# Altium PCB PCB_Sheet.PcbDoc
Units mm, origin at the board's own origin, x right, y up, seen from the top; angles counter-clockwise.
Board outline 50.61 x 50.61 mm, 2 copper layers (Top Layer, Bottom Layer); 8 components, 17 nets, 42 pads, 0 vias.
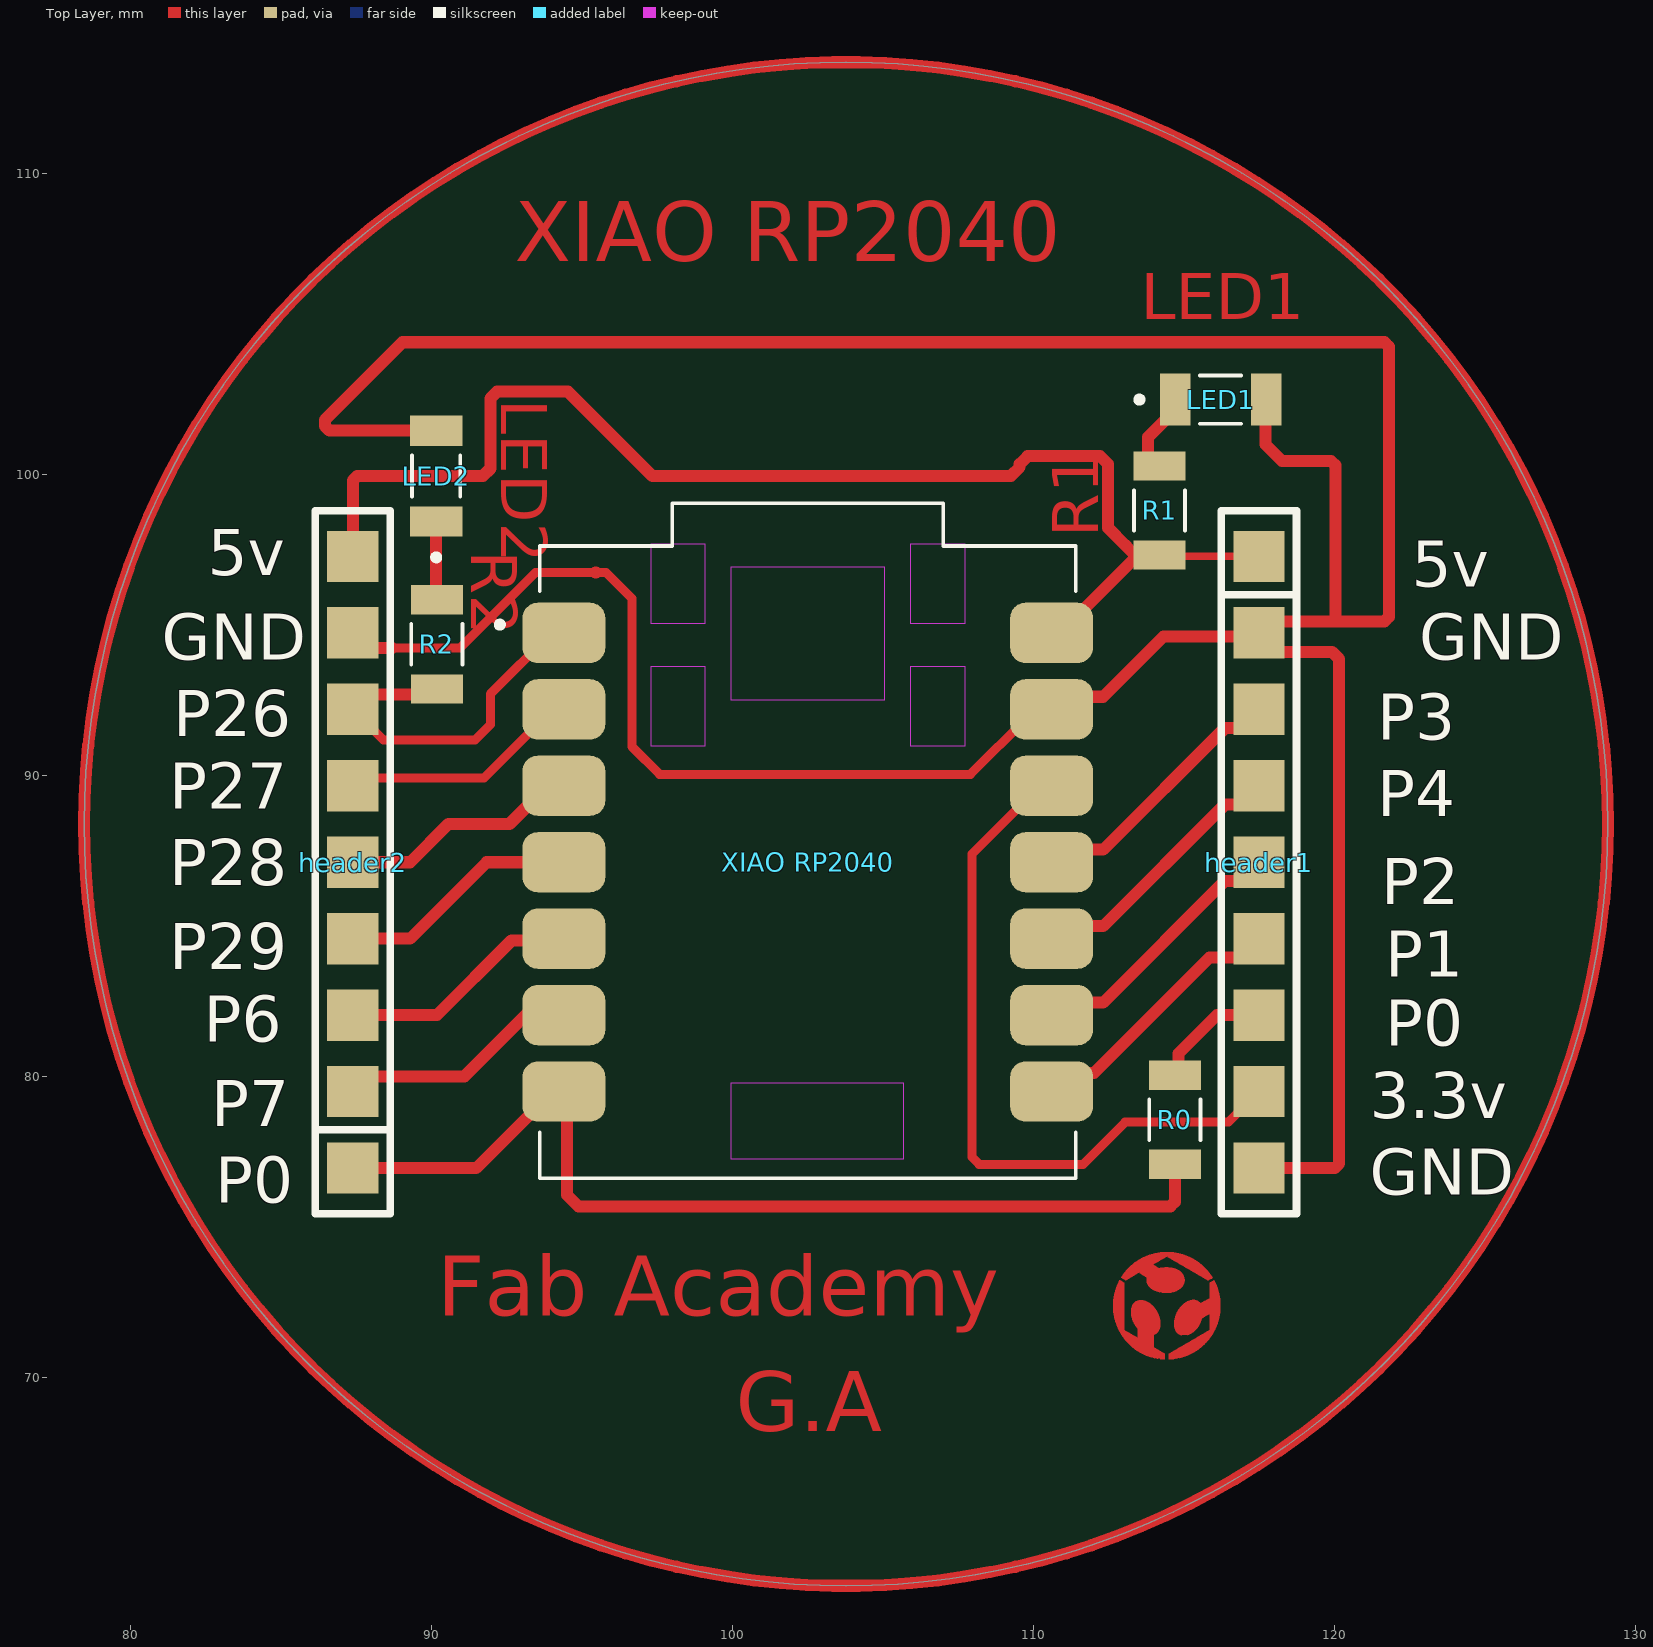
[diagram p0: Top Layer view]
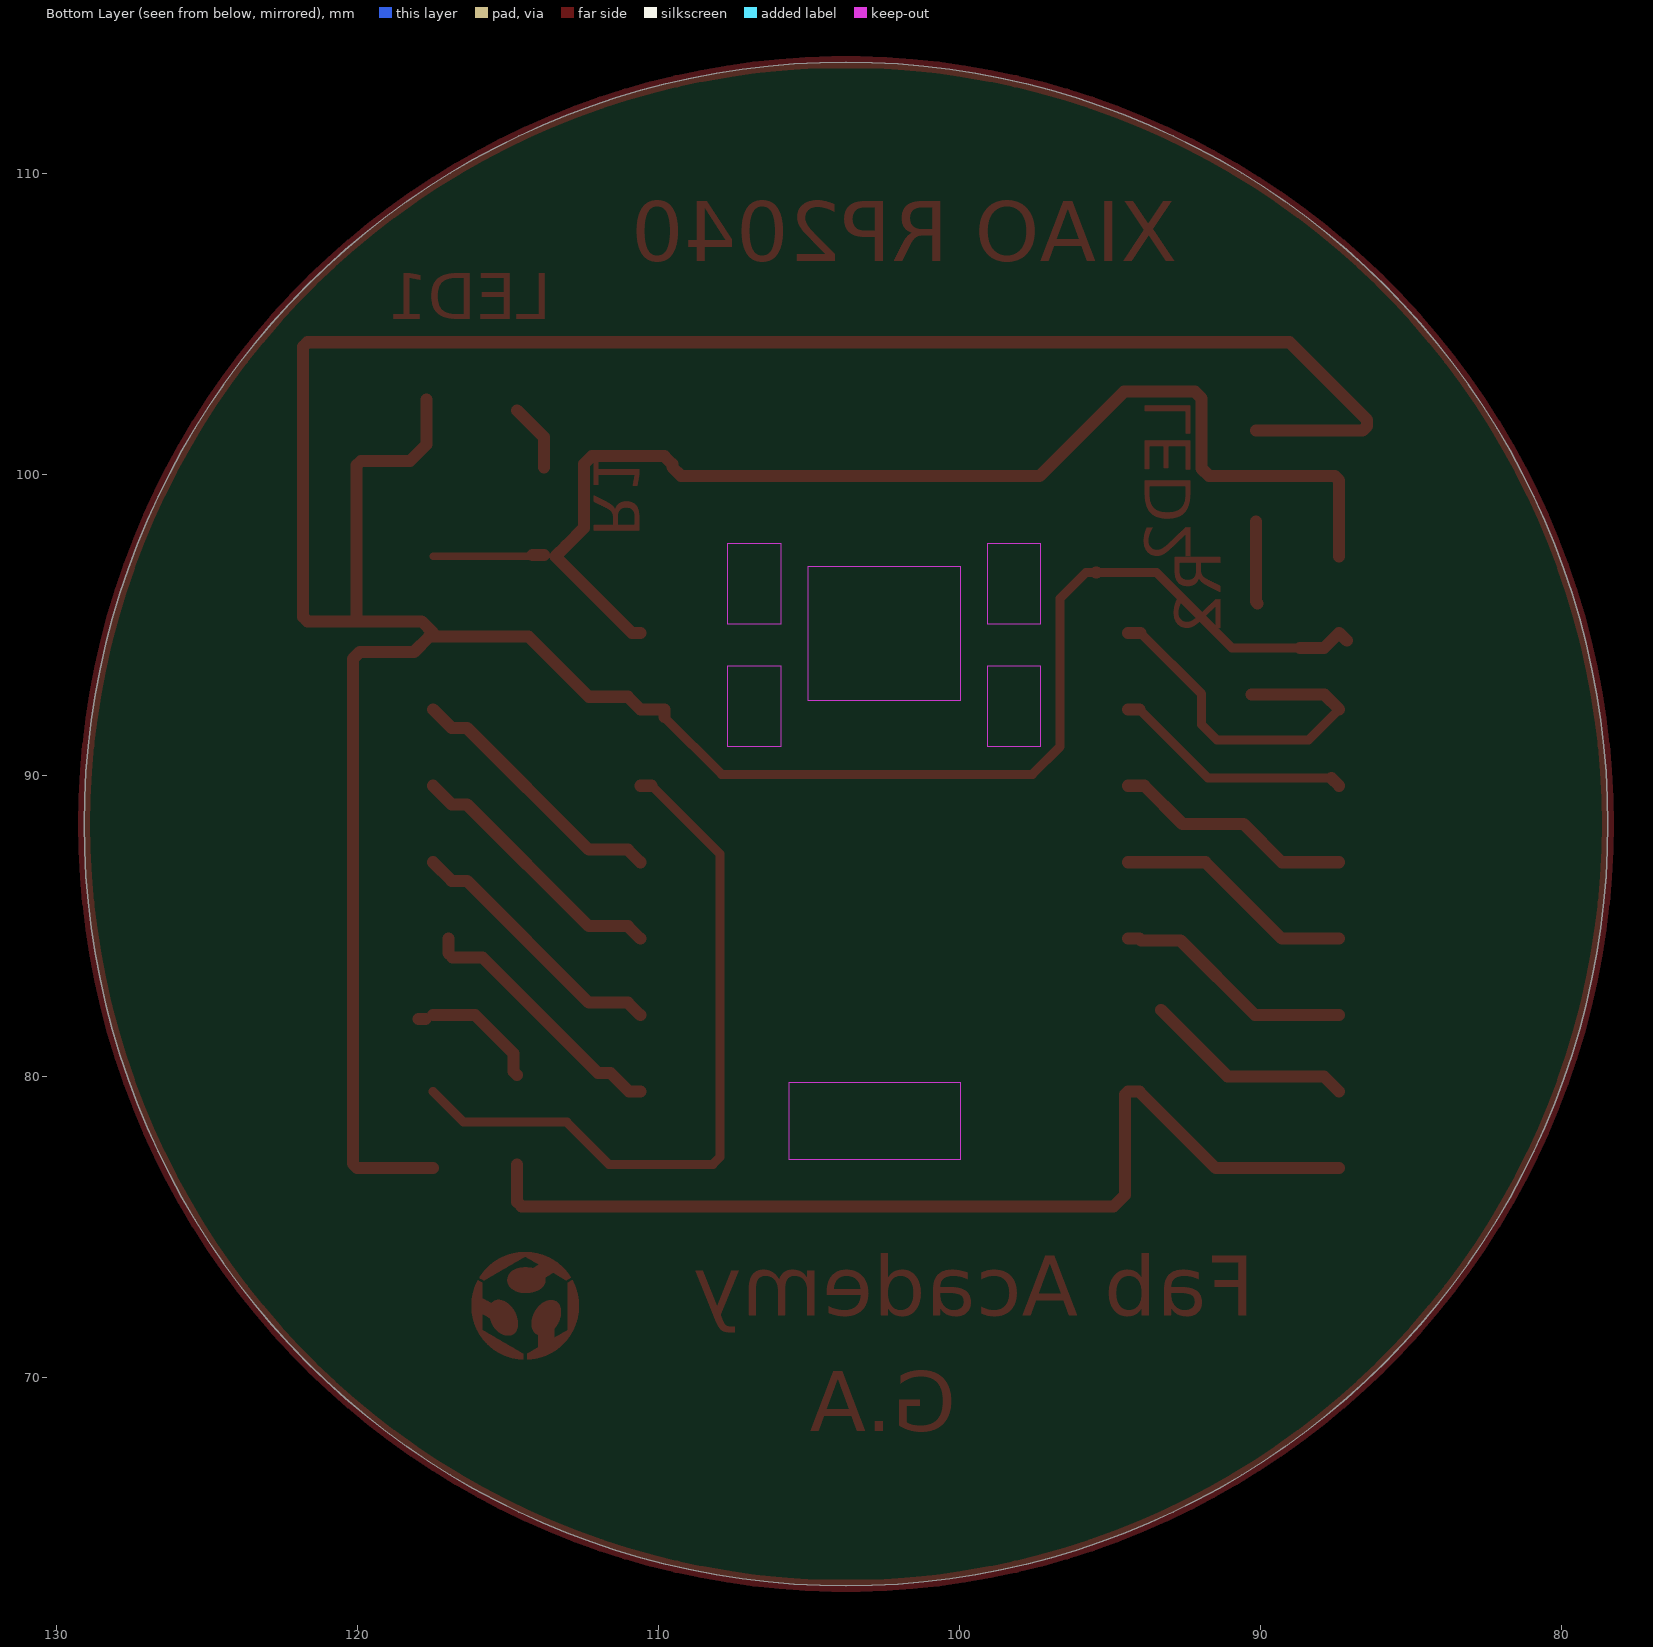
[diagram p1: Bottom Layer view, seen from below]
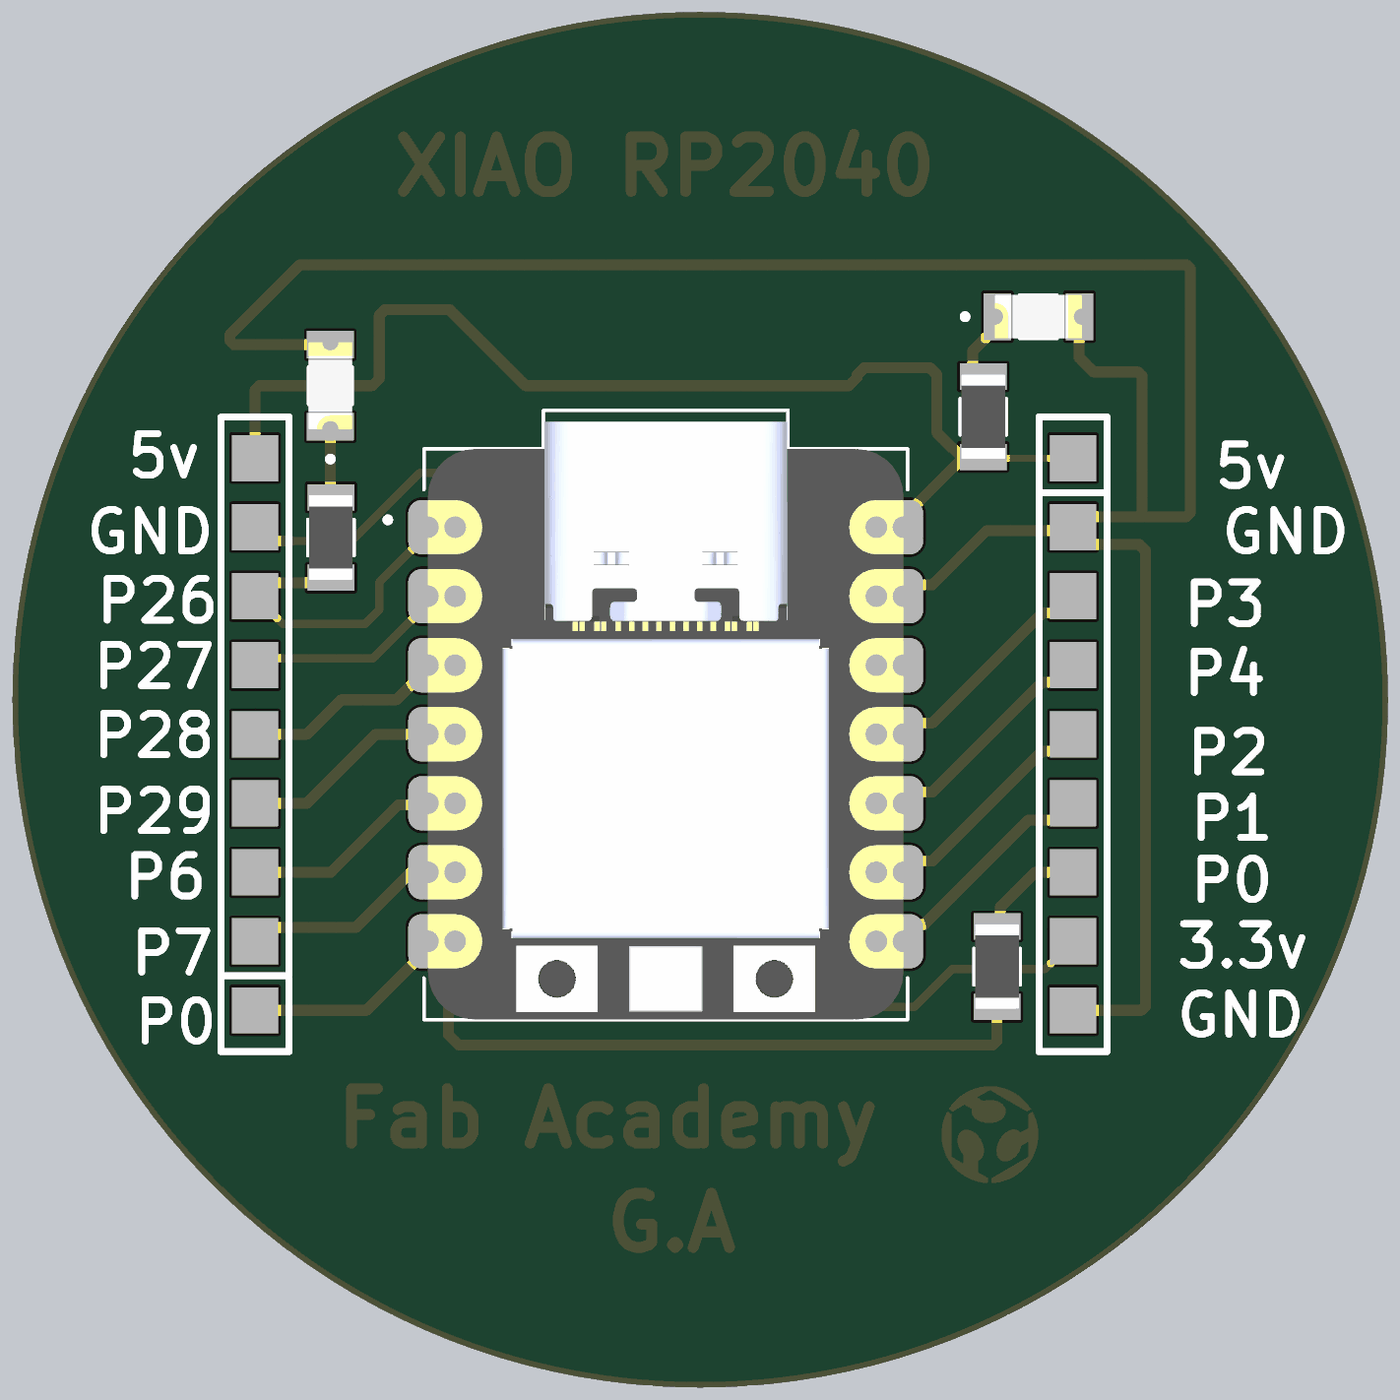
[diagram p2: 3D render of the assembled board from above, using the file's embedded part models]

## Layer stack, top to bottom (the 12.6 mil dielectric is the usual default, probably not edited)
Top Solder: solder mask 0.0102, Solder Resist, Dk 3.5
Top Layer: signal copper 0.0356
Dielectric 1: dielectric 0.32, FR-4, Dk 4.8
Bottom Layer: signal copper 0.0356
Bottom Solder: solder mask 0.0102, Solder Resist, Dk 3.5

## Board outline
78.453,88.392 ccw(c103.759,88.392) 103.759,63.086 ccw(c103.759,88.392) 129.065,88.392 ccw(c103.759,88.392) 103.759,113.698 ccw(c103.759,88.392)

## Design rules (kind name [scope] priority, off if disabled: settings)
Clearance [All] p1: gap=0.254 ignorepadtopadclearanceinfootprint=FALSE except(0: Arc-Hole Track-Hole SMDPad-Hole THPad-Hole Via-Hole Fill-Hole Poly-Hole Region-Hole Text-Hole)
PolygonConnect [All] p1: connectstyle=Relief reliefconductorwidth=0.254 reliefentries=4 polygonreliefangle="90 Angle" airgapwidth=0.254
RoutingVias [All] p1: holewidth=0.711 width=1.27 viastyle="Through Hole" minholewidth=0.711 minwidth=1.27 maxholewidth=0.711 maxwidth=1.27
SolderMaskExpansion [All] p1: expansion=0.102 istentingtop=FALSE
Width [All] p1: maxlimit=0.254 minlimit=0.254 preferedwidth=0.254
30 further rules are at their usual default settings.

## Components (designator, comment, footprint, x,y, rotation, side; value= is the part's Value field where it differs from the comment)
header1 "2.54-1*9P母" 2.54-1*9 117.308,88.448 r270 top
header2 "2.54-1*9P母" 2.54-1*9 87.543,85.796 r90 top
LED1 "LHN974_RED_LED_1206" LED2 116.205,102.489 r0 top
LED2 "LHN974_RED_LED_1206" LED2 90.147,99.949 r90 top
R0 "1k" 1k 114.681,78.569 r270 top
R1 "1k" 1k 114.173,98.806 r90 top
R2 "1k" 1k 90.17,94.361 r270 top
"XIAO RP2040" "102010428" 102010428 102.489,87.122 r0 top (schematic designator RP2040)

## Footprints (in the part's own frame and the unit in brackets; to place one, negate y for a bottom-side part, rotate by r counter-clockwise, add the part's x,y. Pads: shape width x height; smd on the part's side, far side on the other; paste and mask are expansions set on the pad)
1k [mm]
  rect 0.97x1.73 smd: 1(-1.48,0) 2(1.48,0)
  silkscreen extent -0.67,-0.85 0.67,0.85, body extent -1.55,-0.8 1.55,0.8, height 0.65
2.54-1*9 [mm]
  rect 1.7x1.7 smd: 1(-8.834,0.167) 2(-6.294,0.167) 3(-3.754,0.167) 4(-1.214,0.167) 5(1.326,0.167) 6(3.866,0.167) 7(6.406,0.167) 8(8.946,0.167) 9(11.486,0.167)
  silkscreen extent -10.35,-1.08 13.01,1.42
102010428 [mm]
  rrect50% 2.75x2 smd: 1(-8.1,7.62) 2(-8.1,5.08) 3(-8.1,2.54) 4(-8.1,0) 5(-8.1,-2.54) 6(-8.1,-5.08) 7(-8.1,-7.62) 8(8.1,-7.62) 9(8.1,-5.08) 10(8.1,-2.54) 11(8.1,0) 12(8.1,2.54) 13(8.1,5.08) 14(8.1,7.62)
  Keep-Out Layer region: 2.54,5.375 -2.54,5.375 -2.54,9.82 2.54,9.82
  Keep-Out Layer region: 5.207,7.915 3.429,7.915 3.429,10.582 5.207,10.582
  Keep-Out Layer region: 5.207,3.851 3.429,3.851 3.429,6.518 5.207,6.518
  Keep-Out Layer region: -3.429,3.851 -5.207,3.851 -5.207,6.518 -3.429,6.518
  Keep-Out Layer region: -3.429,7.915 -5.207,7.915 -5.207,10.582 -3.429,10.582
  Keep-Out Layer region: 3.175,-9.865 -2.54,-9.865 -2.54,-7.325 3.175,-7.325
  silkscreen extent -10.33,-10.5 8.9,11.92, body extent -8.75,-10.5 8.75,11.5, height 4.41
LED2 [mm] "LEDC3216X120N"
  rect 1.01x1.73 smd: NEG(1.51,0) POS(-1.51,0)
  silkscreen extent -2.8,-0.8 0.68,0.8, body extent -1.6,-0.8 1.6,0.8, height 1.2

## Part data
header1 header2: library part 2.54-1*9, JLCPCB Part Class="Extended Part", LCSC Part Name="间距:2.54mm 1x9P 直插", Manufacturer=BOOMELE(博穆精密)
LED1 LED2: library part LED2, "2.6 V Red LED SMD", Package=None
R0 R1 R2: "Res Thick Film 3.2 x 1.6 mm 6.8K Ohm 1% 0.25W(1/4W) 100ppm/ C Molded SMD Paper T/R", Package=None
"XIAO RP2040": "RP2040 XIAO RP2040 series ARMÂ® CortexÂ®-M0+ MCU 32-Bit Embedded Evaluation Board", Package=None

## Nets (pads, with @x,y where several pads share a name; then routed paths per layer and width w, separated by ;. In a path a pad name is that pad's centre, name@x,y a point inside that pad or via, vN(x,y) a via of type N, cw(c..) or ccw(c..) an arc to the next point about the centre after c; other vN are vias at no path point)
GND: "XIAO RP2040.13" header1.2 header1.9 header2.8 LED1.NEG LED2.NEG | length 125.3
  Top Layer w0.3: 88.68,94.234 90.932,94.234 93.438,96.74 95.438,96.74 ; 95.449,96.752 95.78,96.752 96.647,95.885 96.647,90.966 97.57,90.043 107.893,90.043 109.792,91.942
  Top Layer w0.4: header2.8@87.122,94.488 header2.8 87.884,94.234 88.68,94.234 ; LED2.NEG 86.6,101.459 86.451,101.608 86.451,101.818 89.027,104.394 121.644,104.394 121.793,104.245 121.793,95.272 121.644,95.123 120.015,95.123 ; 95.438,96.74 95.449,96.752 ; 109.792,91.942 109.792,92.202 110.589,92.202 111.005,92.618 112.303,92.618 114.3,94.615 header1.2@117.602,94.615 ; header1.9 119.993,76.962 120.142,77.111 120.142,93.873 119.908,94.107 118.11,94.107 header1.2@117.602,94.615 ; LED1.NEG@117.701,102.489 117.701,100.993 118.237,100.457 119.866,100.457 120.015,100.308 120.015,95.123 ; header1.2@117.602,94.615 header1.2 117.856,95.123 120.015,95.123
Netheader1_1: "XIAO RP2040.14" header1.1 header2.9 R1.1 | length 42.8
  Top Layer w0.254: R1.1 114.217,97.282 header1.1
  Top Layer w0.4: header2.9 87.376,99.8 87.525,99.949 91.694,99.949 91.948,100.203 91.948,102.533 92.171,102.756 94.519,102.756 97.326,99.949 109.234,99.949 109.528,100.243 109.528,100.347 109.794,100.613 112.202,100.613 112.468,100.347 112.468,98.225 113.053,97.64 ; 110.589,94.742 110.872,94.742 R1.1@113.412,97.282 ; 113.054,97.64 R1.1@113.411,97.283 ; R1.1@113.792,97.326 R1.1
Netheader1_3: "XIAO RP2040.11" header1.3 | length 9
  Top Layer w0.4: 110.589,87.122 111.005,87.538 112.303,87.538 116.347,91.582 116.855,91.582 header1.3
Netheader1_4: "XIAO RP2040.10" header1.4 | length 9
  Top Layer w0.4: 110.589,84.582 111.005,84.998 112.303,84.998 116.347,89.042 116.855,89.042 header1.4
Netheader1_5: "XIAO RP2040.9" header1.5 | length 9
  Top Layer w0.4: 110.589,82.042 111.005,82.458 112.303,82.458 116.347,86.502 116.855,86.502 header1.5
Netheader1_6: "XIAO RP2040.8" header1.6 | length 8.8
  Top Layer w0.4: 110.589,79.502 110.964,79.502 111.579,80.117 111.994,80.117 115.839,83.962 116.825,83.962 116.967,84.104 header1.6@116.967,84.582
Netheader1_7: header1.7 R0.1 | length 4.2
  Top Layer w0.4: R0.1 114.799,80.167 114.799,80.763 116.078,82.042 header1.7 ; header1.7@117.729,81.915 header1.7@117.964,81.915
Netheader1_8: "XIAO RP2040.12" header1.8 | length 24.3
  Top Layer w0.3: 110.214,89.662 107.95,87.398 107.95,77.323 108.184,77.089 111.633,77.089 113.03,78.486 116.459,78.486 header1.8
  Top Layer w0.4: 110.214,89.662 110.589,89.662
Netheader2_1: "XIAO RP2040.7" header2.1 R0.2 | length 33.2
  Top Layer w0.4: header2.1 91.474,76.962 94.014,79.502 94.389,79.502 94.488,79.403 94.488,76.073 94.869,75.692 114.532,75.692 114.681,75.841 R0.2
Netheader2_2: "XIAO RP2040.6" header2.2 | length 7
  Top Layer w0.4: header2.2 87.884,80.01 91.086,80.01 93.295,82.219
Netheader2_3: "XIAO RP2040.5" header2.3 | length 8.4
  Top Layer w0.4: header2.3 90.17,82.042 92.648,84.52 93.952,84.52 94.014,84.582 ; 94.014,84.582 94.389,84.582 94.014,84.582
Netheader2_4: "XIAO RP2040.4" header2.4 | length 8.1
  Top Layer w0.4: header2.4 89.281,84.582 91.821,87.122 94.389,87.122
Netheader2_5: "XIAO RP2040.3" header2.5 | length 8.1
  Top Layer w0.4: header2.5 89.281,87.122 90.551,88.392 92.582,88.392 93.852,89.662 94.389,89.662
Netheader2_6: "XIAO RP2040.2" header2.6 | length 8.1
  Top Layer w0.3: header2.6@87.63,89.916 91.728,89.916 94.014,92.202
  Top Layer w0.4: header2.6 header2.6@87.63,89.916 ; 94.014,92.202 94.389,92.202
Netheader2_7: "XIAO RP2040.1" header2.7 R2.2 | length 12.6
  Top Layer w0.3: header2.7 88.392,91.186 91.44,91.186 91.948,91.694 91.948,92.71 93.98,94.742
  Top Layer w0.4: header2.7 87.868,92.694 R2.2@90.297,92.694 ; 93.98,94.742 94.389,94.742
NetLED1_POS: LED1.POS R1.2 | length 2.3
  Top Layer w0.4: R1.2@113.792,100.242 113.792,101.24 LED1.POS@114.681,102.129
NetLED2_POS: LED2.POS R2.1 | length 2.7
  Top Layer w0.4: R2.1@90.085,95.718 90.147,95.781 LED2.POS
copper on no net: | length 159
  Top Layer w0.4: 129.065,88.392 ccw(c103.759,88.392) 129.065,88.392

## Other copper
Top Layer:
  region: 2297 vertices and 0 holes, not listed, extent 112.635,70.607 114.351,73.239
  region: 1962 vertices and 0 holes, not listed, extent 112.903,72.818 115.933,74.169
  region: 2267 vertices and 0 holes, not listed, extent 114.472,70.607 116.197,73.23
  text "Fab Academy" at 90.189,72.059 h2
  text "G.A" at 100.095,68.218 h2

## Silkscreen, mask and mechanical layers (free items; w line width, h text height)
Top Overlay:
  text "5v" at 82.55,96.647 h1.52
  text "5v" at 122.555,96.266 h1.52
  text "GND" at 81.026,93.853 h1.52
  text "GND" at 122.809,93.853 h1.52
  text "P26" at 81.407,91.313 h1.52
  text "P3" at 121.412,91.186 h1.52
  text "P27" at 81.28,88.9 h1.52
  text "P4" at 121.412,88.646 h1.52
  text "P28" at 81.28,86.36 h1.52
  text "P2" at 121.539,85.725 h1.52
  text "P29" at 81.28,83.566 h1.52
  text "P1" at 121.666,83.312 h1.52
  text "P6" at 82.423,81.153 h1.52
  text "P0" at 121.666,81.026 h1.52
  text "3.3v" at 121.158,78.613 h1.52
  text "P7" at 82.677,78.359 h1.52
  text "GND" at 121.158,76.073 h1.52
  text "P0" at 82.804,75.819 h1.52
